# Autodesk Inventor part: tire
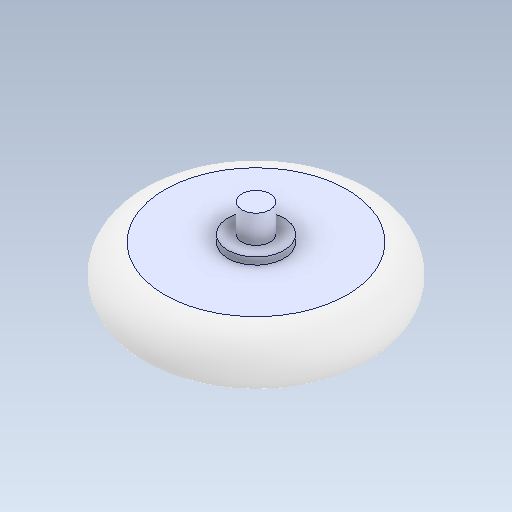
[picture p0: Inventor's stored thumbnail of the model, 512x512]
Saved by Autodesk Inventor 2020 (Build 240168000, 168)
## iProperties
Created: 2017-04
Part Number: tire
Material: Générique
Document SubType Name: Modeling
Designer: bruno
Density: 1 g/cm^3
Appearance: Par défaut
Author: bruno
Sending System: SolidWorks 2016
Last Author: Samartha
Last Saved: 2017-04-03
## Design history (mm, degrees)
fillet "Fillet3"
node "Solide1"
